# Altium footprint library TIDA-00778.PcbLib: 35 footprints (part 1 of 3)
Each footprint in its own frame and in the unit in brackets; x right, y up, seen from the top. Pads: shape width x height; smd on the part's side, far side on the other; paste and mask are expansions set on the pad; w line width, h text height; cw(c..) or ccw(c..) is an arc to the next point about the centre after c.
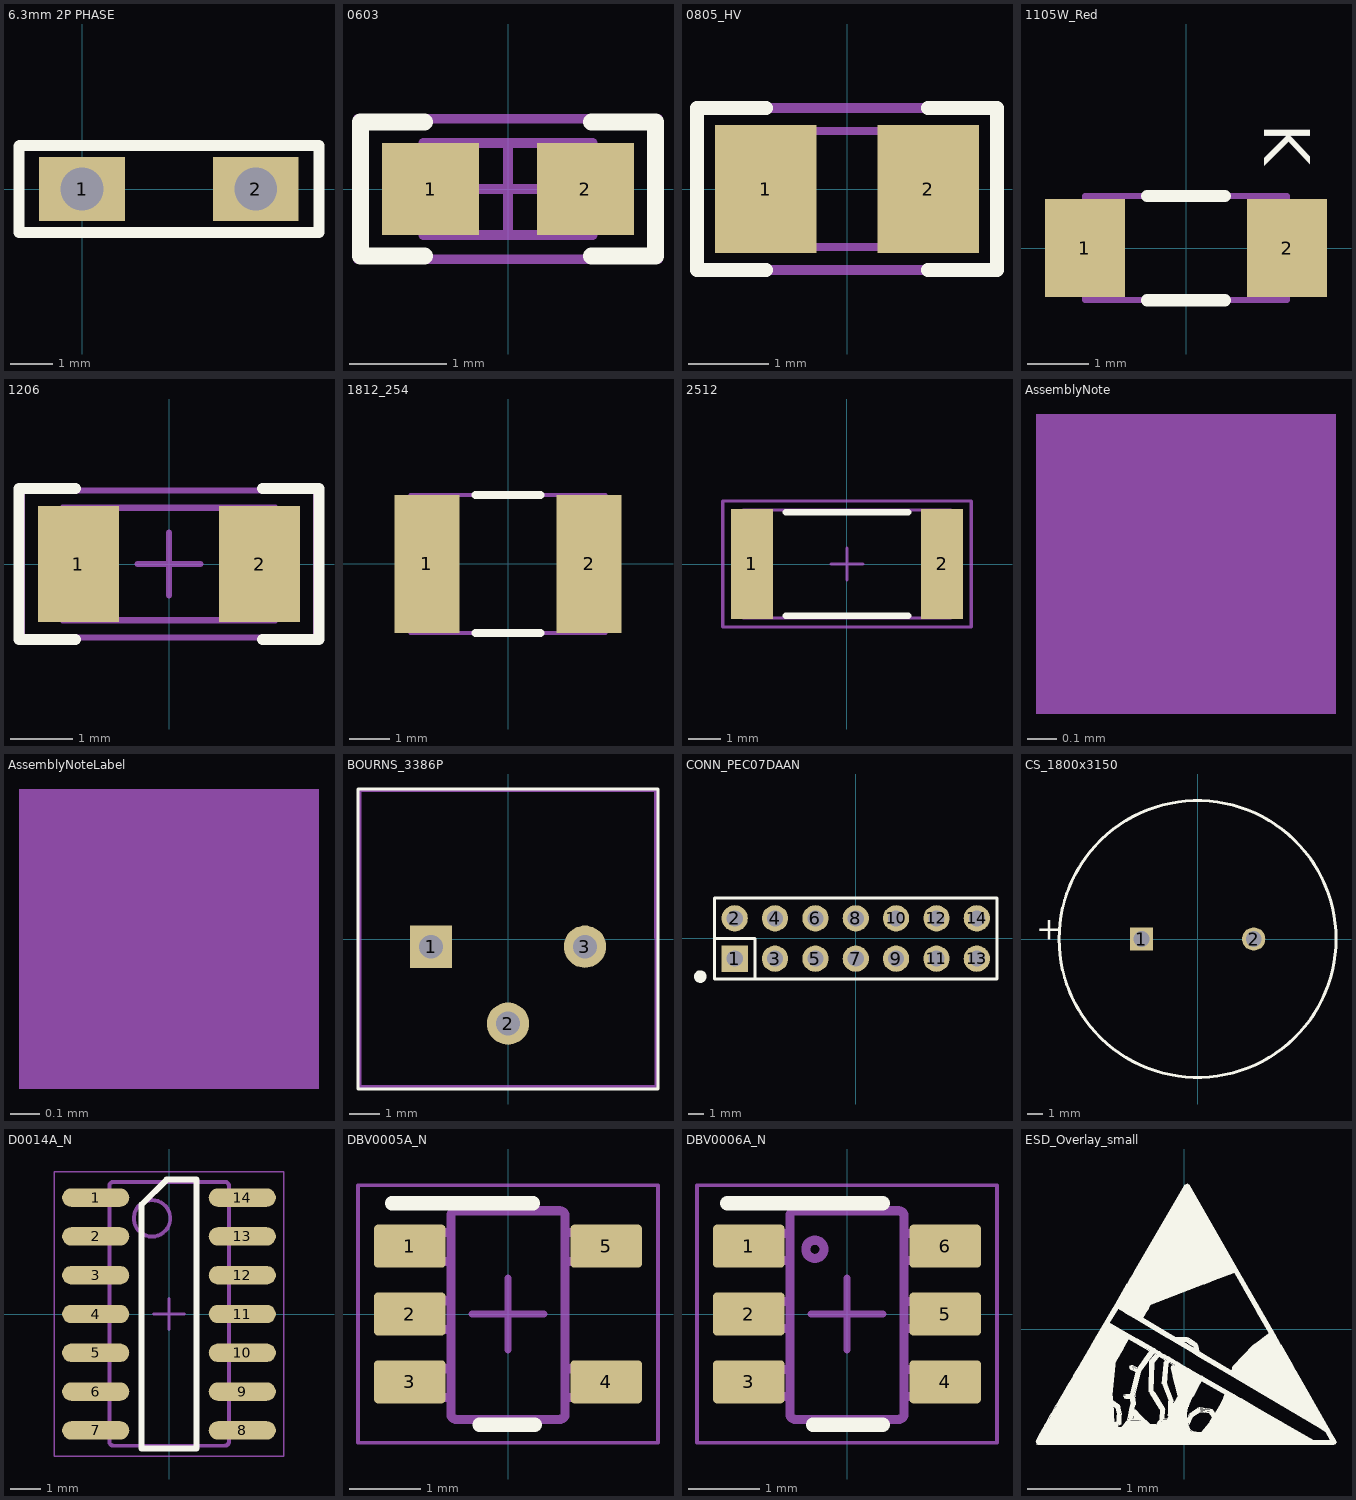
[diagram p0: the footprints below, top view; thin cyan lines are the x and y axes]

## 6.3mm 2P PHASE [mm]
pads (2):
  rect 2x1.5 hole 1 square: 1(0,0) 2(4.06,0)
Top Overlay:
  lines w0.254: -1.473,-1.016 5.537,-1.016 5.537,1.016 -1.448,1.016 ccw(c-1.448,0.991) -1.473,0.991 -1.473,-1.016

## 0603 [mm] "0603 from SM-752 data"
height 1
pads (2):
  rect 1x0.95 smd: 1(-0.8,0) 2(0.8,0)
Top Overlay:
  lines w0.178: -0.864,-0.691 -1.524,-0.691 -1.524,0.693 -0.864,0.693 ; 0.864,-0.691 1.524,-0.691 1.524,0.693 0.864,0.693
Mechanical 5:
  lines w0.1: -1.55,-0.725 1.55,-0.725 1.55,0.725 -1.55,0.725 -1.55,-0.725
  text ".Designator" at -1.397,-0.381 h0.76
Mechanical 13:
  lines w0.1: -0.55,-0.475 -0.55,0.475 ; 0.55,-0.475 0.55,0.475 ; -0.875,-0.475 -0.875,0.475 0.875,0.475 0.875,-0.475 -0.875,-0.475
Mechanical 15:
  lines w0.1: -0.475,0 0.475,0 ; 0,-0.475 0,0.475 ; -1.55,-0.725 -1.55,0.725 1.55,0.725 1.55,-0.725 -1.55,-0.725
3D body: height 1, standoff 0, extent 0.551,-0.474 0.874,0.474
3D body: height 1, standoff 0, extent -0.549,-0.474 0.549,0.474
3D body: height 1, standoff 0, extent -0.874,-0.474 -0.551,0.474

## 0805_HV [mil] "0805 with 30mil clearance between pads"
height 57.09
pads (2):
  rect 50x63 smd: 1(-40,0) 2(40,0)
Top Overlay:
  lines w7: -40,-40 -74,-40 -74,0 -74,40 -40,40 ; 40,-40 74,-40 74,0 74,40 40,40
Mechanical 5:
  lines w5: -74,-40 -74,40 74,40 74,-40 -74,-40
  text ".Designator" at -64,-17 h35
Mechanical 13:
  lines w3.94: -25.59,-28.54 -25.59,28.54 ; 25.59,-28.54 25.59,28.54 ; -43.31,-28.54 -43.31,28.54 43.31,28.54 43.31,-28.54 -43.31,-28.54
3D body: height 57.09, standoff 0, extent 25.61,-28.52 43.29,28.52
3D body: height 57.09, standoff 0, extent -25.57,-28.52 25.57,28.52
3D body: height 57.09, standoff 0, extent -43.29,-28.52 -25.61,28.52

## 1105W_Red [mm] "Stanley Electric Co"
height 2.05
pads (2):
  rect 1.3x1.6 smd: 1(-1.65,0) 2(1.65,0)
Top Overlay:
  lines w0.2: -0.635,-0.85 0.635,-0.85 ; -0.635,0.85 0.635,0.85
  text "K" at 1.281,2.032 h0.75
Mechanical 5:
  lines w0.1: -1.65,-0.85 1.65,-0.85 1.65,0.85 -1.65,0.85 -1.65,-0.85
  text "K" at 1.993,-0.33 h0.76
  text ".Designator" at -0.776,-0.305 h0.76
3D body: height 0.41, standoff 0.4, extent 0.902,0.401 1.3,0.8
3D body: height 1.25, standoff 0.4, extent -0.794,-0.798 0.8,0.799
3D body: height 2.05, standoff 0.45, extent -0.792,-0.797 0.8,0.797
3D body: height 0.4, standoff 0, extent -1.65,-0.85 1.65,0.85

## 1206 [mm] "1206 from SM-752 data"
height 1.35
pads (2):
  rect 1.3x1.85 smd: 1(-1.45,0) 2(1.45,0)
Top Overlay:
  lines w0.178: -1.5,-1.21 -2.4,-1.21 -2.4,1.21 -1.5,1.21 ; 1.5,-1.21 2.4,-1.21 2.4,1.21 1.5,1.21
Mechanical 5:
  lines w0.1: -1.7,-0.9 1.7,-0.9 1.7,0.9 -1.7,0.9 -1.7,-0.9
  text ".Designator" at 0.826,0.451 h0.76
Mechanical 13:
  lines w0.1: -1.2,-0.9 -1.2,0.9 ; 1.2,-0.9 1.2,0.9 ; -1.7,-0.9 1.7,-0.9 1.7,0.9 -1.7,0.9 -1.7,-0.9
Mechanical 15:
  lines w0.1: -0.5,0 0.5,0 ; 0,-0.5 0,0.5 ; -2.35,-1.175 2.35,-1.175 2.35,1.175 -2.35,1.175 -2.35,-1.175
3D body: height 1.35, standoff 0, extent -1.699,-0.899 -1.201,0.899
3D body: height 1.35, standoff 0, extent -1.199,-0.899 1.199,0.899
3D body: height 1.35, standoff 0, extent 1.201,-0.899 1.699,0.899

## 1812_254 [mm] "SMD, 2-Leads, Body 4.8x3.4mm"
height 2.54
pads (2):
  rect 1.6x3.4 smd: 1(-2,0) 2(2,0)
Top Overlay:
  lines w0.2: -0.8,-1.7 0.8,-1.7 ; -0.8,1.7 0.8,1.7
Mechanical 5:
  lines w0.1: -1.9,-1.7 -1.9,1.7 ; 1.9,-1.7 1.9,1.7 ; -2.4,-1.7 2.4,-1.7 2.4,1.7 -2.4,1.7 -2.4,-1.7
  text ".Designator" at -1.875,-0.5 h0.76
3D body: height 2.54, standoff 0, extent -2.399,-1.699 -1.901,1.699
3D body: height 2.54, standoff 0, extent -1.899,-1.699 1.899,1.699
3D body: height 2.54, standoff 0, extent 1.901,-1.699 2.399,1.699

## 2512 [mm] "Chip Resistor, Body 6.3x3.2mm, IPC Medium Density"
height 0.71
pads (2):
  rect 1.3x3.4 smd: 1(-2.95,0) 2(2.95,0)
Top Overlay:
  lines w0.2: -1.9,-1.6 1.9,-1.6 ; -1.9,1.6 1.9,1.6
Mechanical 5:
  lines w0.1: -3.225,-1.675 3.225,-1.675 3.225,1.675 -3.225,1.675 -3.225,-1.675
  text ".Designator" at 0.65,0.433 h0.76
Mechanical 13:
  lines w0.1: -2.463,-1.675 -2.463,1.675 ; 2.463,-1.675 2.463,1.675 ; -3.225,-1.675 3.225,-1.675 3.225,1.675 -3.225,1.675 -3.225,-1.675
Mechanical 15:
  lines w0.1: -0.5,0 0.5,0 ; 0,-0.5 0,0.5 ; -3.85,-1.95 3.85,-1.95 3.85,1.95 -3.85,1.95 -3.85,-1.95
3D body: height 0.71, standoff 0, extent -3.224,-1.674 -2.464,1.674
3D body: height 0.71, standoff 0, extent -2.462,-1.674 2.462,1.674
3D body: height 0.71, standoff 0, extent 2.464,-1.674 3.224,1.674

## AssemblyNote [mm] "Assembly Note"
Mechanical 5:
  rectangle: 15.9,83.109 16.916,84.125
  text ".Designator" at 12.065,83.033 h0.76
  text ".Comment" at 17.475,83.16 h0.76

## AssemblyNoteLabel [mm] "Assembly Note for PCB Labels"
Mechanical 5:
  rectangle: 15.799,83.744 16.815,84.76
  text "Install label in silkscreened box after final wash.  Text shall be 8 pt font.  Text shall be per the Label Table in the PDF schematic." at 17.755,83.896 h0.76
  text ".Designator" at 11.913,83.845 h0.76

## BOURNS_3386P [mil] "BOURND"
height 200
pads (3):
  rect 55x55 hole 31: 1(-100,-10)
  round 55 hole 31: 2(0,-110) 3(100,-10)
Top Overlay:
  lines w4: -195,-195 195,-195 195,195 -195,195 -195,-195
Mechanical 5:
  lines w4: -192.5,-192 192.5,-192 192,193 -192.5,193 -192.5,-192
  text ".Designator" at -80,-20 h40
3D body: height 201, standoff 0, extent -54.98,-49.98 44.98,49.98
3D body: height 200, standoff 0, extent -192.52,-192.02 192.52,193.02
3D body: height 50, standoff -200, extent -10.91,-120.98 11,-99.02
3D body: height 50, standoff -200, extent -110.91,-20.97 -89,0.99
3D body: height 50, standoff -200, extent 89.09,-20.97 111,0.99

## CONN_PEC07DAAN [mm] "SULLINS"
height 8.382
pads (14):
  rect 1.65x1.65 hole 1.016 mask+0: 1(-7.62,-1.27)
  round 1.65 hole 1.016 mask+0: 2(-7.62,1.27) 3(-5.08,-1.27) 4(-5.08,1.27) 5(-2.54,-1.27) 6(-2.54,1.27) 7(0,-1.27) 8(0,1.27) 9(2.54,-1.27) 10(2.54,1.27) 11(5.08,-1.27) 12(5.08,1.27) 13(7.62,-1.27) 14(7.62,1.27)
Top Overlay:
  circle w0.381: c-9.79,-2.4 r0.203
  lines w0.178: -8.89,0 -6.35,0 -6.35,-2.54 ; -8.89,-2.54 8.89,-2.54 8.89,2.54 -8.89,2.54 -8.89,-2.54
Mechanical 5:
  rectangle: -8.128,-1.778 -7.112,-0.762
  lines w0.076: -8.89,-2.54 8.89,-2.54 8.89,2.54 -8.89,2.54 -8.89,-2.54
  lines w0.127: -8.89,-2.54 -8.89,2.54 8.89,2.54 8.89,-2.54 -8.89,-2.54
  text ".Designator" at -1.778,-0.508 h1.02
3D body: height 2.54, standoff 0, extent -8.954,-2.603 8.954,2.603
3D body: height 11.43, standoff -3.05, extent -7.937,-1.587 -7.302,-0.952
3D body: height 11.43, standoff -3.05, extent -7.937,0.953 -7.302,1.588
3D body: height 11.43, standoff -3.05, extent -5.397,0.953 -4.762,1.588
3D body: height 11.43, standoff -3.05, extent -5.397,-1.587 -4.762,-0.952
3D body: height 11.43, standoff -3.05, extent -2.857,-1.587 -2.222,-0.952
3D body: height 11.43, standoff -3.05, extent -2.857,0.953 -2.222,1.588
3D body: height 11.43, standoff -3.05, extent -0.317,-1.587 0.318,-0.952
3D body: height 11.43, standoff -3.05, extent -0.317,0.953 0.318,1.588
3D body: height 11.43, standoff -3.05, extent 2.223,-1.587 2.858,-0.952
3D body: height 11.43, standoff -3.05, extent 7.303,-1.587 7.938,-0.952
3D body: height 11.43, standoff -3.05, extent 7.303,0.953 7.938,1.588
3D body: height 11.43, standoff -3.05, extent 4.763,0.953 5.398,1.588
3D body: height 11.43, standoff -3.05, extent 4.763,-1.587 5.398,-0.952
3D body: height 11.43, standoff -3.05, extent 2.223,0.953 2.858,1.588

## CS_1800x3150 [mm] "TH, 2-Leads, Body 18x31.5mm, Pin Spacing 7.5mm"
height 33.5
pads (2):
  rect 1.55x1.55 hole 1.05: 1(-3.75,0)
  round 1.55 hole 1.05: 2(3.75,0)
Top Overlay:
  circle w0.2: c0,0 r9.25
  text "+" at -10.795,-0.049 h1.5
Mechanical 5:
  circle w0.1: c0,0 r9.25
  text ".Designator" at 0,-0.811 h0.76
  text "+" at -9.906,2.491 h0.76
3D body: height 0, standoff -2.5, extent 3.353,-0.399 4.15,0.399
3D body: height 0, standoff -2.5, extent -4.147,-0.399 -3.35,0.399
3D body: height 33.5, standoff 0, extent 6.061,-4.626 9.245,4.625
3D body: height 33.5, standoff 0, extent -9.249,-9.261 8.01,9.261
3D body: height 33.5, standoff 0, extent -6.999,-7.008 7,7.007

## D0014A_N [mm] "SOIC, 14-Leads, Body 8.7x3.9mm, Pitch 1.27mm, IPC Medium Density"
height 1.75
pads (14):
  oval 2.2x0.6 smd: 1(-2.4,3.81) 2(-2.4,2.54) 3(-2.4,1.27) 4(-2.4,0) 5(-2.4,-1.27) 6(-2.4,-2.54) 7(-2.4,-3.81) 8(2.4,-3.81) 9(2.4,-2.54) 10(2.4,-1.27) 11(2.4,0) 12(2.4,1.27) 13(2.4,2.54) 14(2.4,3.81)
Top Overlay:
  lines w0.2: -0.9,-4.4 0.9,-4.4 0.9,4.4 -0.075,4.4 -0.9,3.575 -0.9,-4.4
Mechanical 5:
  drawing of 164 lines, arcs and shapes, not listed
  text ".Designator" at 0.711,0.203 h0.76
Mechanical 15:
  lines w0.05: -3.75,-4.65 3.75,-4.65 3.75,4.65 -3.75,4.65 -3.75,-4.65
  lines w0.1: -0.5,0 0.5,0 ; 0,-0.5 0,0.5
3D body "SOIC-14akaD0014AakaM14A.stp": height 1.59, standoff -0.01, extent -3.023,-4.318 3.022,4.318

## DBV0005A_N [mm] "SOT23, 5-Leads, Body 2.9x1.6mm, Pitch 0.95mm, Lead Span 2.8mm, IPC Medium Density"
height 1.45
pads (5):
  rrect17% 1x0.6 smd: 1(-1.375,0.95) 2(-1.375,0) 3(-1.375,-0.95) 4(1.375,-0.95) 5(1.375,0.95)
Top Overlay:
  lines w0.2: -1.625,1.55 0.35,1.55 ; -0.4,-1.55 0.375,-1.55
Mechanical 5:
  lines w0.127: -0.801,1.371 cw(c-0.725,1.37) -0.725,1.446 ; -0.801,1.37 -0.801,-1.399 -0.801,-1.4 ccw(c-0.725,-1.399) -0.725,-1.475 ; -0.801,1.37 -0.801,1.371 ; -0.725,-1.475 -0.725,-1.475 ; -0.725,-1.475 0.723,-1.475 0.724,-1.475 ccw(c0.723,-1.399) 0.799,-1.4 0.799,-1.399 0.799,1.37 ; -0.725,1.446 0.723,1.446 0.724,1.446 cw(c0.723,1.37) 0.799,1.371 ; -0.725,1.446 -0.725,1.446 ; 0.799,1.37 0.799,1.371 ; -1.423,-1.167 -1.199,-1.167 -1.105,-1.167 -1.088,-1.167 -0.835,-1.167 -0.801,-1.167 -0.801,-0.767 -0.835,-0.767 -1.088,-0.767 -1.105,-0.767 -1.199,-0.767 -1.423,-0.767 -1.423,-1.167 ; -1.423,-0.215 -1.199,-0.215 -1.105,-0.215 -1.088,-0.215 -0.835,-0.215 -0.801,-0.215 -0.801,0.186 -0.835,0.186 -1.088,0.186 -1.105,0.186 -1.199,0.186 -1.423,0.186 -1.423,-0.215 ; -1.423,0.738 -1.199,0.738 -1.105,0.738 -1.088,0.738 -0.835,0.738 -0.801,0.738 -0.801,1.138 -0.835,1.138 -1.088,1.138 -1.105,1.138 -1.199,1.138 -1.423,1.138 -1.423,0.738 ; 0.799,-1.167 0.799,-0.767 0.834,-0.767 1.087,-0.767 1.103,-0.767 1.198,-0.767 1.422,-0.767 1.422,-1.167 1.198,-1.167 1.103,-1.167 1.087,-1.167 0.834,-1.167 0.799,-1.167 ; 0.799,0.738 0.799,1.138 0.834,1.138 1.087,1.138 1.103,1.138 1.198,1.138 1.422,1.138 1.422,0.738 1.198,0.738 1.103,0.738 1.087,0.738 0.834,0.738 0.799,0.738
  text ".Designator" at -0.25,0.95 h0.51
Mechanical 15:
  lines w0.05: -2.1,-1.8 2.1,-1.8 2.1,1.8 -2.1,1.8 -2.1,-1.8
  lines w0.1: -0.5,0 0.5,0 ; 0,-0.5 0,0.5
3D body "DBV0005A.stp": height 1.09, standoff 0, extent -1.422,-1.461 1.423,1.46

## DBV0006A_N [mm] "SOT23, 6-Leads, Body 2.9x1.6mm, Pitch 0.95mm, Lead Span 2.8mm, IPC Medium Density"
height 1.45
pads (6):
  rrect17% 1x0.6 smd: 1(-1.375,0.95) 2(-1.375,0) 3(-1.375,-0.95) 4(1.375,-0.95) 5(1.375,0) 6(1.375,0.95)
Top Overlay:
  lines w0.2: -1.675,1.55 0.5,1.55 ; -0.475,-1.55 0.5,-1.55
Mechanical 5:
  lines w0.127: 0.724,-1.475 ccw(c0.723,-1.399) 0.8,-1.399 0.8,1.37 ccw(c0.723,1.37) 0.724,1.446 ; 0.723,-1.475 -0.724,-1.475 -0.725,-1.475 cw(c-0.724,-1.399) -0.801,-1.399 -0.801,1.37 cw(c-0.724,1.37) -0.725,1.446 -0.724,1.446 0.723,1.446 ; 0.723,-1.475 0.724,-1.475 ; 0.723,1.446 0.724,1.446 ; -1.423,-1.154 -1.423,-0.78 -1.206,-0.78 -1.113,-0.78 -1.081,-0.78 -0.828,-0.78 -0.801,-0.78 -0.801,-1.154 -0.828,-1.154 -1.081,-1.154 -1.113,-1.154 -1.206,-1.154 -1.423,-1.154 ; -1.423,-0.202 -1.423,0.173 -1.206,0.173 -1.113,0.173 -1.081,0.173 -0.828,0.173 -0.801,0.173 -0.801,-0.202 -0.828,-0.202 -1.081,-0.202 -1.113,-0.202 -1.206,-0.202 -1.423,-0.202 ; -1.423,0.751 -1.423,1.125 -1.206,1.125 -1.113,1.125 -1.081,1.125 -0.828,1.125 -0.801,1.125 -0.801,0.751 -0.828,0.751 -1.081,0.751 -1.113,0.751 -1.206,0.751 -1.423,0.751 ; -0.577,0.906 ccw(c-0.45,0.906) -0.323,0.906 ccw(c-0.45,0.906) -0.577,0.906 ; 0.8,-1.154 0.8,-0.78 0.827,-0.78 1.08,-0.78 1.112,-0.78 1.205,-0.78 1.422,-0.78 1.422,-1.154 1.205,-1.154 1.112,-1.154 1.08,-1.154 0.827,-1.154 0.8,-1.154 ; 0.8,-0.202 0.8,0.173 0.827,0.173 1.08,0.173 1.112,0.173 1.205,0.173 1.422,0.173 1.422,-0.202 1.205,-0.202 1.112,-0.202 1.08,-0.202 0.827,-0.202 0.8,-0.202 ; 0.8,0.751 0.8,1.125 0.827,1.125 1.08,1.125 1.112,1.125 1.205,1.125 1.422,1.125 1.422,0.751 1.205,0.751 1.112,0.751 1.08,0.751 0.827,0.751 0.8,0.751
  text ".Designator" at -0.298,0.455 h0.76
Mechanical 15:
  lines w0.05: -2.1,-1.8 -2.1,1.8 2.1,1.8 2.1,-1.8 -2.1,-1.8
  lines w0.1: -0.5,0 0.5,0 ; 0,-0.5 0,0.5
3D body "DBV0006A.stp": height 1.12, standoff 0, extent -1.422,-1.461 1.423,1.46

## ESD_Overlay_small [mm]
Top Overlay:
  drawing of 901 lines, arcs and shapes, not listed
